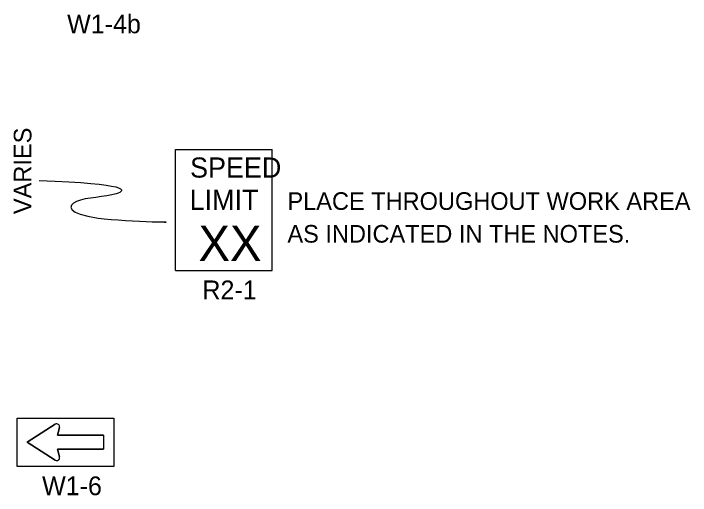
# Model space of a CAD drawing. Extents: x 16525 to 18475, y 5726 to 6926.
# Drawn here: x 17159.3 to 17428.3, y 6361.6 to 6552.9 of the extents above; entities that cross this region are included whole.
import ezdxf

# ---------------------------------------------------------------- set-up
doc = ezdxf.new("R2010")
doc.units = 0
doc.layers.add('TRAFFIC_SIGNS_PR', color=7, linetype='Continuous')
doc.layers.add('TYPICAL_TEXT_DIMEN_PR', color=7, linetype='Continuous')

msp = doc.modelspace()

# ---------------------------------------------------------------- linework, layer by layer
at = {"layer": 'TRAFFIC_SIGNS_PR'}
for p, q in [((17223.67, 6498.93), (17262.07, 6498.93)), ((17223.67, 6450.93), (17223.67, 6498.93)), ((17262.07, 6450.93), (17262.07, 6498.93)), ((17223.67, 6450.93), (17262.07, 6450.93)), ((17175.84, 6389.81), (17164.68, 6382.7)), ((17176.69, 6385.5), (17177.52, 6388.56)), ((17195.08, 6385.5), (17176.69, 6385.5)), ((17195.08, 6385.5), (17195.08, 6379.9)), ((17164.68, 6382.7), (17175.84, 6375.6)), ((17177.52, 6376.84), (17176.69, 6379.9)), ((17176.69, 6379.9), (17195.08, 6379.9))]:
    msp.add_line(p, q, dxfattribs=at)
msp.add_lwpolyline([(17199.08, 6373.1), (17160.68, 6373.1), (17160.68, 6392.3), (17199.08, 6392.3)], close=True, dxfattribs=at)
for points in [[(17175.84, 6375.6), (17164.68, 6382.7), (17175.84, 6389.81)], [(17177.52, 6388.56), (17176.69, 6385.5), (17195.08, 6385.5), (17195.08, 6379.9), (17176.69, 6379.9), (17177.52, 6376.84)]]:
    msp.add_lwpolyline(points, dxfattribs=at)
for centre, start, end in [((17176.44, 6388.86), 344.6731, 122.4696), ((17176.44, 6388.86), 344.6731, 122.4696), ((17176.44, 6376.55), 237.5304, 15.3269), ((17176.44, 6376.55), 237.5304, 15.3269)]:
    msp.add_arc(centre, 1.12, start, end, dxfattribs=at)
at = {"layer": 'TYPICAL_TEXT_DIMEN_PR'}
msp.add_open_spline([(17169.45, 6486.6), (17205.37, 6485.47), (17203.46, 6479.98), (17180.48, 6479.98), (17180.48, 6470.08), (17230.12, 6470.08), (17215.43, 6470.08)], degree=3, dxfattribs=at)

# ---------------------------------------------------------------- texts
at = {"layer": 'TRAFFIC_SIGNS_PR'}
for s, height, p in [('W1-4b', 7.44, (17180.57, 6545.11)), ('SPEED', 8, (17229.43, 6487.79)), ('LIMIT', 8, (17229.27, 6474.99)), ('PLACE THROUGHOUT WORK AREA', 7, (17268.13, 6474.97)), ('XX', 14.031, (17232.78, 6454.69)), ('AS INDICATED IN THE NOTES.', 7, (17268.13, 6461.97)), ('R2-1', 7.44, (17234.34, 6439.49)), ('W1-6', 7.44, (17170.62, 6361.66))]:
    msp.add_text(s, height=height, dxfattribs=at).set_placement(p)
at = {"layer": 'TYPICAL_TEXT_DIMEN_PR'}
msp.add_text('VARIES', height=7, rotation=90, dxfattribs=at).set_placement((17166.38, 6473.3))

doc.saveas('drawing.dxf')
